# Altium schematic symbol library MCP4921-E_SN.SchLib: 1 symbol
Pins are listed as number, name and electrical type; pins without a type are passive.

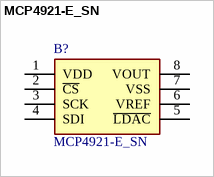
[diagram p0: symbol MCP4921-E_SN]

## MCP4921-E_SN
designator B?
Single 12-bit DAC SPI I/F,MCP4921-E/SN; Manufacturer_Name: Microchip; Geometry.Height: 1.75mm
footprint SOIC127P600X175-8N
pins: 1 VDD, 2 ~{CS}, 3 SCK, 4 SDI, 5 ~{LDAC}, 6 VREF, 7 VSS, 8 VOUT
